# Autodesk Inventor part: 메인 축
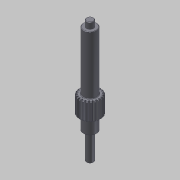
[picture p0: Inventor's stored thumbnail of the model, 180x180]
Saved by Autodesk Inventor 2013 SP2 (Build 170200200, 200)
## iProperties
Created: 2016-02
Part Number: 메인 축
Material: 강철, 연강
Document SubType Name: Modeling
Categories: <?xml version="1.0" encoding="UTF-16"?> <MemberInstance><Categories><FamilyTemplate><FamilyTemplateParameter ValueType="xs:double" Id="1" ObjectReferenceKey="da
Density: 7.86 g/cm^3
Mass: 187.503 g
Surface Area: 82.0529 cm^2
Volume: 23.8554 cm^3
CustomPartVersion: 1
Author: mdu
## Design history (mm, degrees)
sketch "Sketch1"
  geometry: C1 r 12 at (0, 0)
  constraints: 1 centre point
  dimensions: "d0" = 24 diameter of C1 (= da_da)
extrude "Extrusion1" new body sketch "Sketch1" distance "d1" = 20 (= da_b); taper "d2" = 0 deg
workplane "Work Plane2"
feature "피치 지름" dims "d4" = 10, "d5" = 0
workplane "Work Plane8"
workplane "Work Plane9"
chamfer "모따기1" distance "d49" = 1; stored, may be unused: second distance "d50" = 2, angle "d51" = 45 deg
sketch "스케치3"
  geometry: C1 r 7.5 at (0, 0); 1 further point
  constraints: 1 centre point, 1 coincident
  dimensions: "d52" = 15 diameter of C1
extrude "돌출2" join sketch "스케치3" distance "d53" = 66; taper "d54" = 0 deg
sketch "스케치4"
  geometry: C1 r 4 at (0, 0); 1 further point
  constraints: 1 centre point, 1 coincident
  dimensions: "d55" = 8 diameter of C1
extrude "돌출3" join sketch "스케치4" distance "d56" = 7; taper "d57" = 0 deg
sketch "스케치5"
  geometry: C1 r 7.5 at (0, 0) reference; C2 r 7.5 at (0, 0) reference; 1 further point
extrude "돌출4" join sketch "스케치5" distance "d62" = 16; taper "d63" = 0 deg
sketch "스케치6"
  geometry: C1 r 4 at (0, 0); 1 further point
  constraints: 1 centre point, 1 coincident
  dimensions: "d64" = 8 diameter of C1
extrude "돌출5" join sketch "스케치6" distance "d65" = 30; taper "d66" = 0 deg
chamfer "모따기2" distance "d58" = 0.5; stored, may be unused: second distance "d59" = 2, angle "d60" = 45 deg
fillet "모깎기1" dims "d61" = 0.5
feature "스퍼 기어" dims "da_b" = 20, "da_d" = 22, "da_aw" = 31, "da_da" = 24, "da_df" = 19.5, "da_dw" = 22, angle "da_beta" = 0 deg, "da_lefttooth" = 0, "da_righttooth" = 0
sketch "스케치7" dims "d68" = 18
  geometry: C1 r 0.25 at (0, -9); 2 further points
  constraints: 2 vertical alignment, 1 centre point, 1 coincident, 2 other
  dimensions: "d67" = 0.5 diameter of C1
extrude "돌출6" join sketch "스케치7" distance "d69" = 0.3; taper "d70" = 0 deg
body "Solid1"
sketch "Sketch2"
  geometry: C1 r 12 at (0, 0) reference; C2 r 11 at (0, 0)
  constraints: 1 centre point, 1 coincident
  dimensions: "d3" = 22 diameter of C2 (= da_dw)
body "Srf1"
node "투영된 루프1"
other parameters: "d16" = 31 (= da_aw), "d17" = 0, "d34" = 1.428 (computed from da_z), "d39" = 0, "d41" = 0, "d43" = 31 (= da_aw), "d46" = 31 (= da_aw), "d47" = 0, "d48" = 0
